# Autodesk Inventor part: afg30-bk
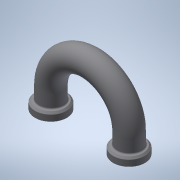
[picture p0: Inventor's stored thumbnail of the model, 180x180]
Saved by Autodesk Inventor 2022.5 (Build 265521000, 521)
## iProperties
Created: 2016-12
Part Number: afg30-bk
Material: 一般
Document SubType Name: Modeling
Designer: imaocorp
Density: 1 g/cm^3
Appearance: 既定
Author: imaocorp
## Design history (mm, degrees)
node "afg30-bk.x_t1"
node "afg30-bk"
node "Base1"
